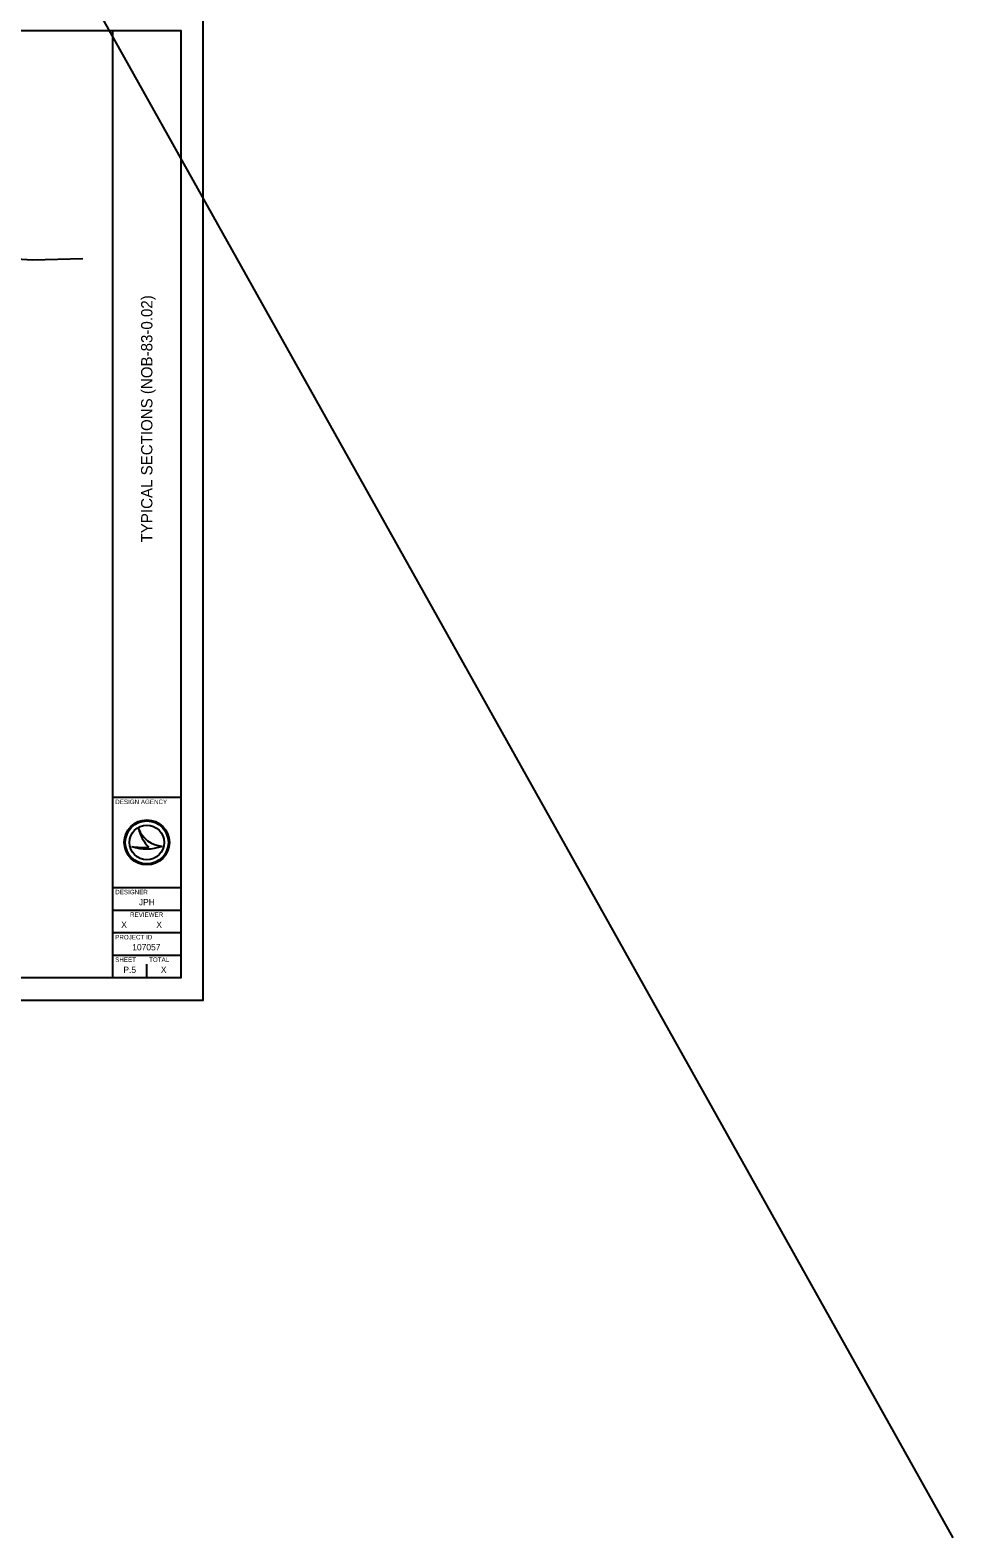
# Model space of a CAD drawing. Extents: x -396 to 156, y -166 to 172.
# Drawn here: x -268.4 to -207.1, y -166.2 to -66 of the extents above; entities that cross this region are included whole.
import ezdxf

# ---------------------------------------------------------------- set-up
doc = ezdxf.new("R2010")
doc.units = 0
for name, color, linetype in [('DT_X_Terrain_Ground_Line', 7, 'Continuous'), ('SH_Border', 7, 'Continuous'), ('SH_Cut_Line', 7, 'Continuous'), ('SH_Data', 7, 'Continuous'), ('XS_P_Finished_Grade', 7, 'Continuous')]:
    doc.layers.add(name, color=color, linetype=linetype)

msp = doc.modelspace()

# ---------------------------------------------------------------- linework, layer by layer
at = {"layer": 'DT_X_Terrain_Ground_Line'}
msp.add_lwpolyline([(-277.72, -80.74), (-276.29, -80.81), (-272.85, -81.1), (-270.39, -81.13), (-268.26, -81.25), (-264.9, -81.17)], dxfattribs=at)
at = {"layer": 'SH_Border'}
for p, q in [((-262.9, -129), (-262.9, -66)), ((-262.9, -117), (-258.4, -117)), ((-262.9, -123), (-258.4, -123)), ((-262.9, -124.5), (-258.4, -124.5)), ((-262.9, -126), (-258.4, -126)), ((-262.9, -127.5), (-258.4, -127.5))]:
    msp.add_line(p, q, dxfattribs=at)
msp.add_lwpolyline([(-354.4, -66), (-258.4, -66), (-258.4, -129), (-354.4, -129)], close=True, dxfattribs=at)
at = {"layer": 'SH_Cut_Line'}
msp.add_lwpolyline([(-358.9, -130.5), (-256.9, -130.5), (-256.9, -64.5), (-358.9, -64.5)], close=True, dxfattribs=at)
at = {"layer": 'SH_Data'}
for p, q in [((-261.2, -119.07), (-261.2, -119.07)), ((-261.65, -120.27), (-261.65, -120.27)), ((-260.65, -120), (-260.65, -120)), ((-259.64, -120.24), (-259.64, -120.24)), ((-260.65, -129), (-260.65, -128.1)), ((-261.78, -128.47), (-261.78, -128.47))]:
    msp.add_line(p, q, dxfattribs=at)
for radius in [1.5, 1.43, 1.43, 1.15]:
    msp.add_circle((-260.65, -120), radius, dxfattribs=at)
for centre, radius, start, end in [((-259.55, -118.5), 1.74, 198.9257, 198.9319), ((-258.86, -118.59), 2.39, 191.6379, 191.6421), ((-259.55, -118.5), 1.74, 198.9319, 267.1657), ((-258.86, -118.59), 2.39, 191.6421, 226.0947), ((-260.68, -117.39), 3.04, 251.4576, 290.0832), ((-260.96, -116.53), 3.8, 259.4964, 259.4995), ((-260.68, -117.39), 3.04, 251.4527, 251.4576), ((-260.96, -116.53), 3.8, 259.4995, 276.6672)]:
    msp.add_arc(centre, radius, start, end, dxfattribs=at)
at = {"layer": 'XS_P_Finished_Grade'}
msp.add_line((-396.1, 171.68), (-207.08, -166.25), dxfattribs=at)

# ---------------------------------------------------------------- texts
at = {"layer": 'SH_Data'}
msp.add_text('TYPICAL SECTIONS (NOB-83-0.02)', height=0.75, rotation=90, dxfattribs=at).set_placement((-260.28, -100.05))
for s, height, p in [('DESIGN AGENCY', 0.3, (-262.75, -117.45)), ('DESIGNER', 0.3, (-262.75, -123.45)), ('JPH', 0.42, (-261.18, -124.18)), ('X', 0.42, (-262.35, -125.68)), ('REVIEWER', 0.3, (-261.77, -124.95)), ('X', 0.42, (-260.02, -125.68)), ('PROJECT ID', 0.3, (-262.75, -126.45)), ('107057', 0.42, (-261.62, -127.18)), ('SHEET', 0.3, (-262.75, -127.95)), ('P.5', 0.42, (-262.21, -128.68)), ('TOTAL', 0.3, (-260.5, -127.95)), ('X', 0.42, (-259.72, -128.68))]:
    msp.add_text(s, height=height, dxfattribs=at).set_placement(p)

doc.saveas('drawing.dxf')
